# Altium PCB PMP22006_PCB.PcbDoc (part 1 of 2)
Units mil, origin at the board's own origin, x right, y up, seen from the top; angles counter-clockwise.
Board outline 2500 x 1522 mil, 4 copper layers (Top Layer, Signal Layer 1, Signal Layer 2, Bottom Layer), stack 186.034 mil thick; 52 components, 32 nets, 135 pads, 25 vias.
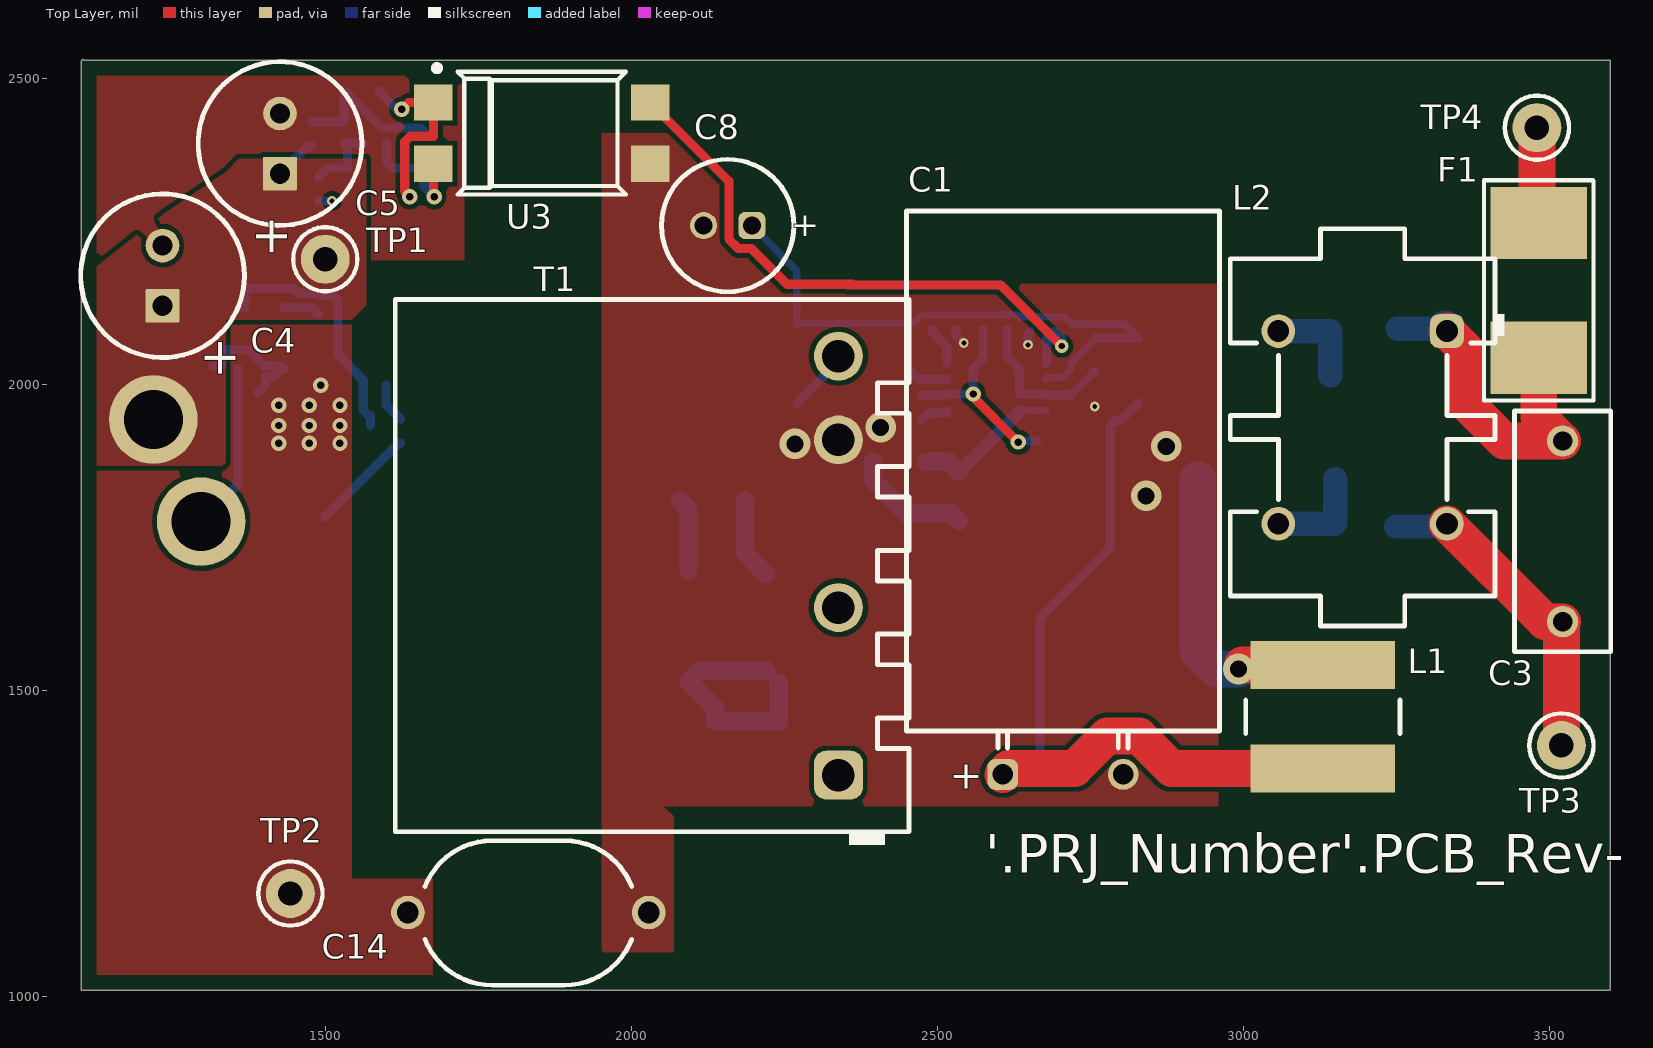
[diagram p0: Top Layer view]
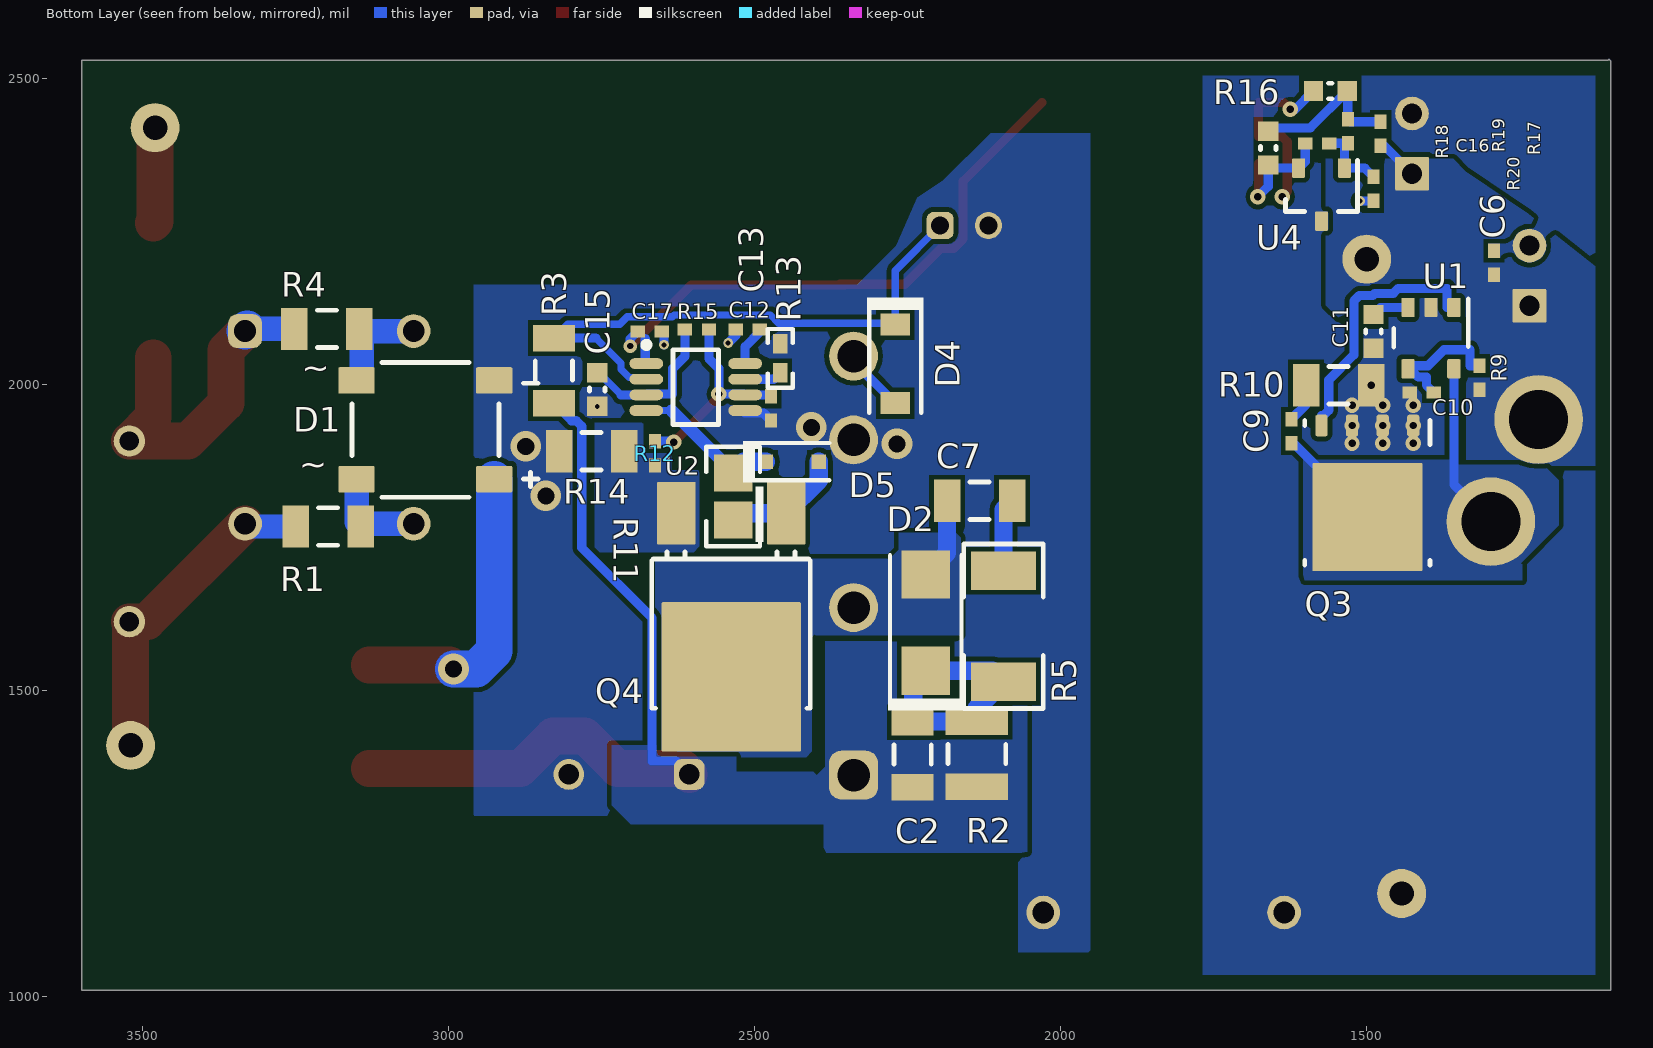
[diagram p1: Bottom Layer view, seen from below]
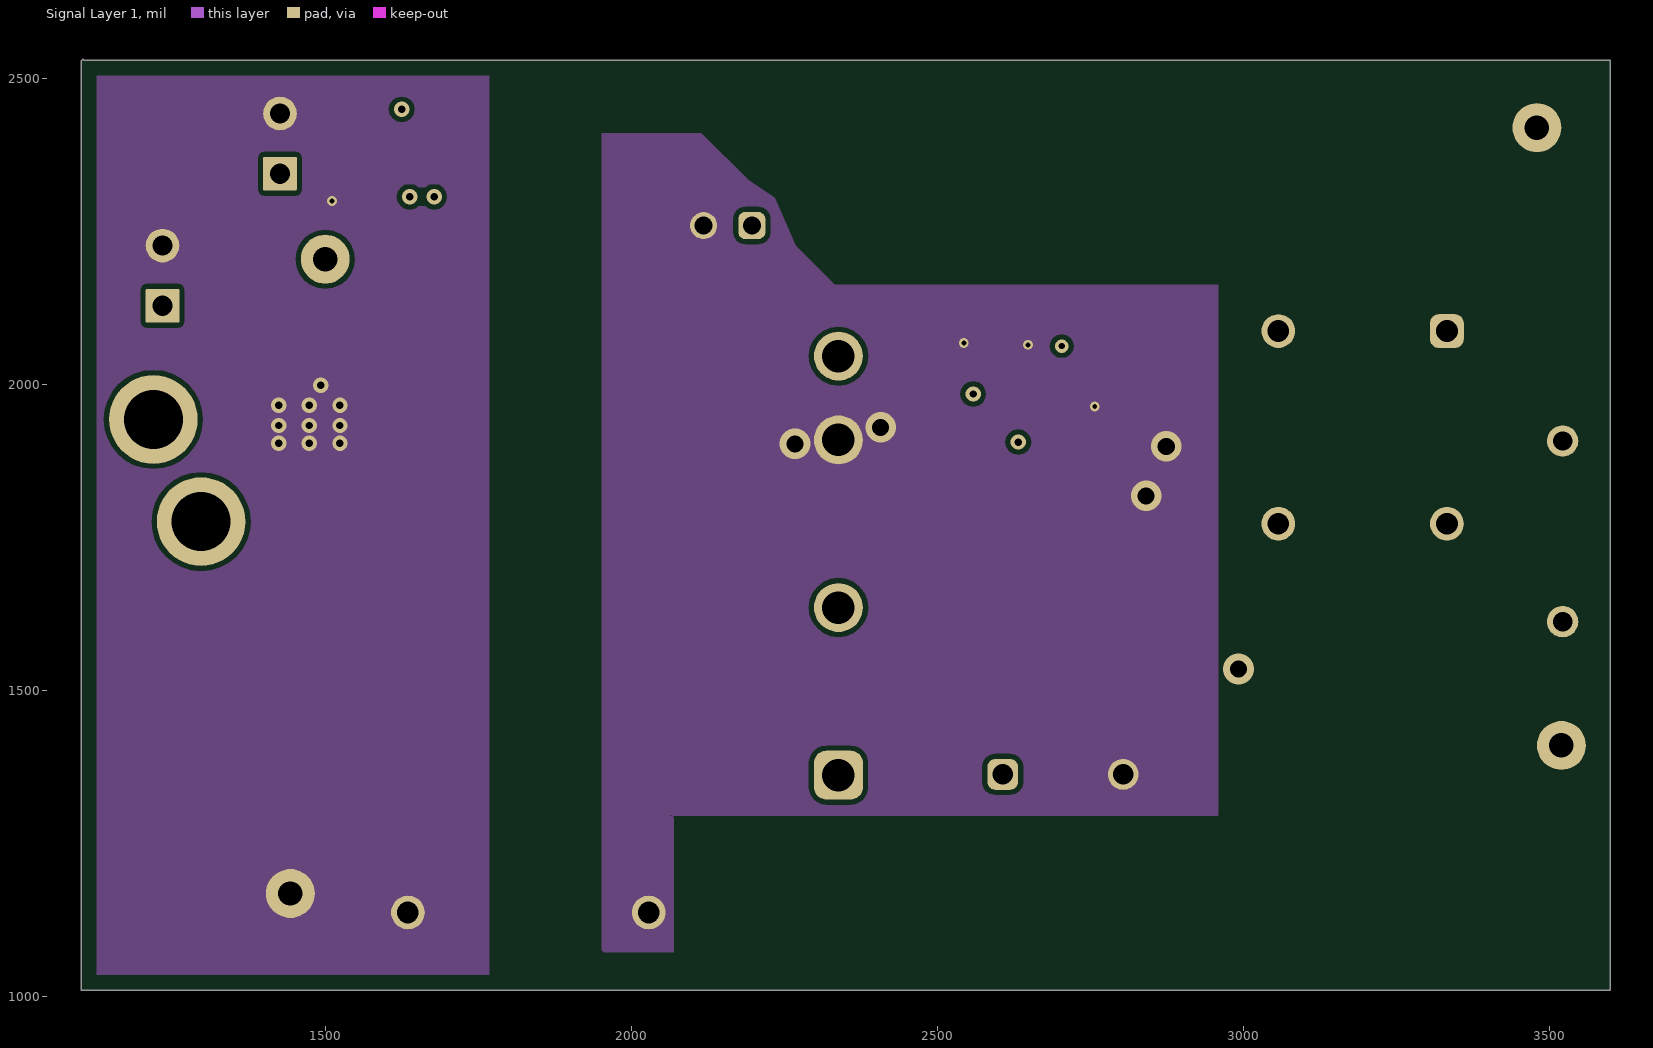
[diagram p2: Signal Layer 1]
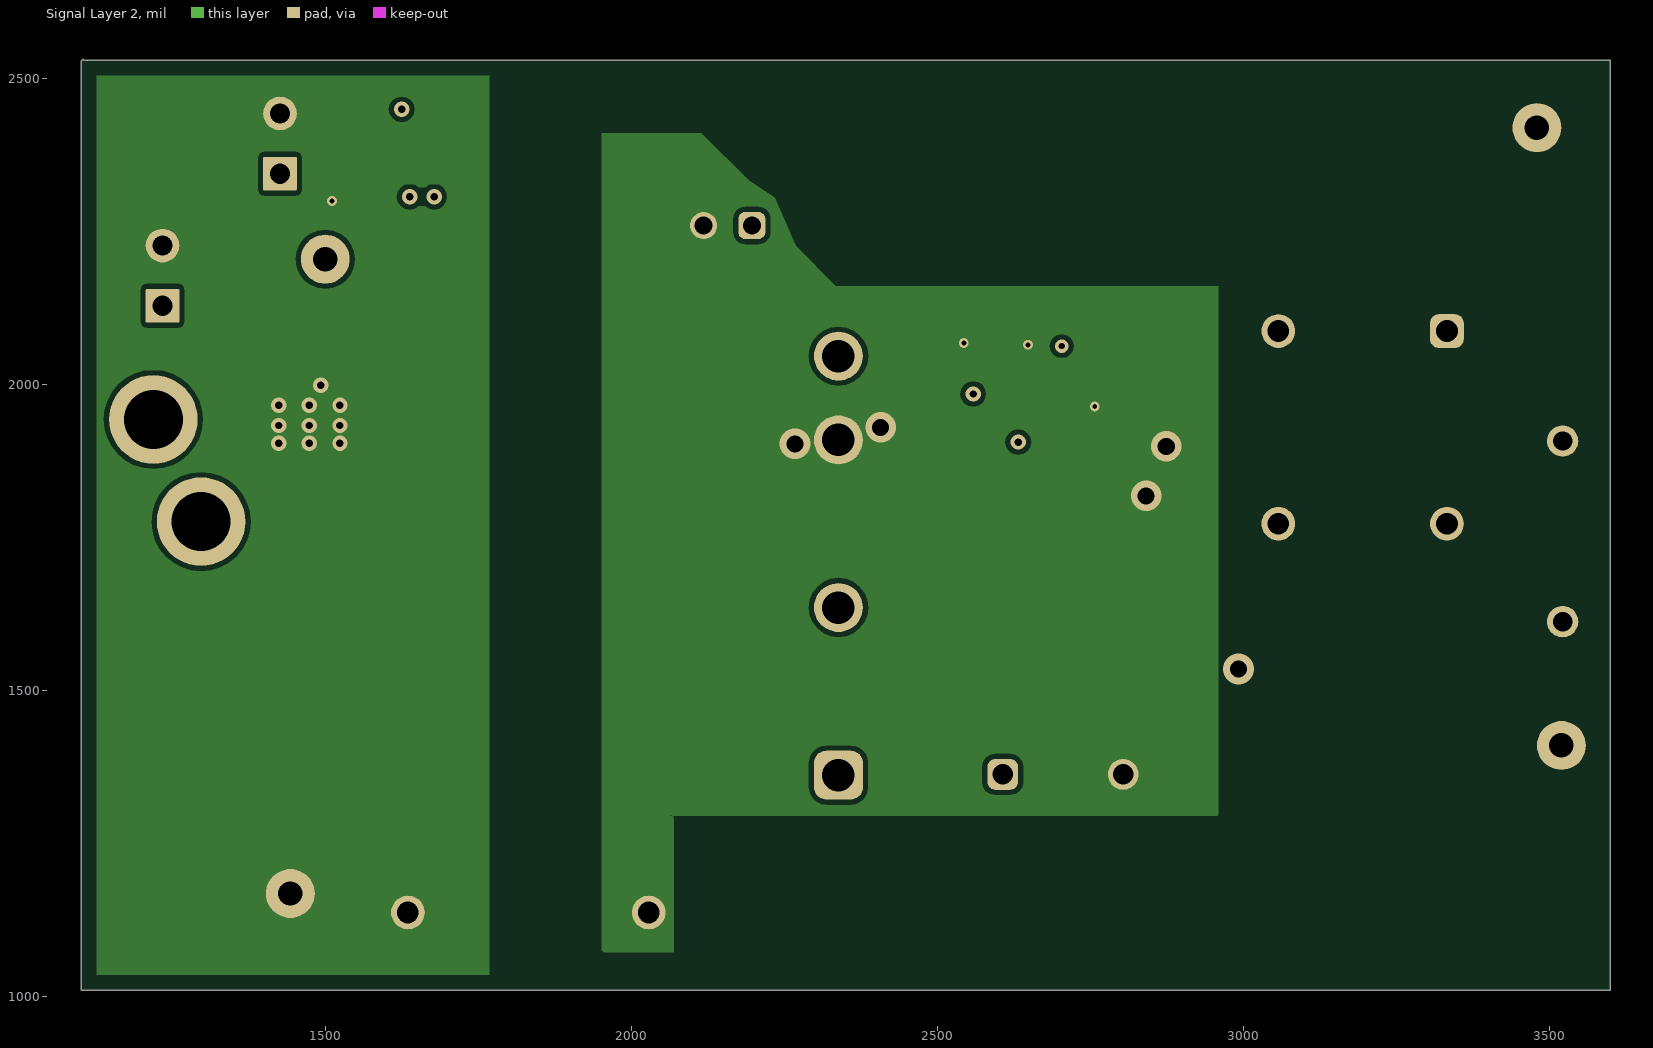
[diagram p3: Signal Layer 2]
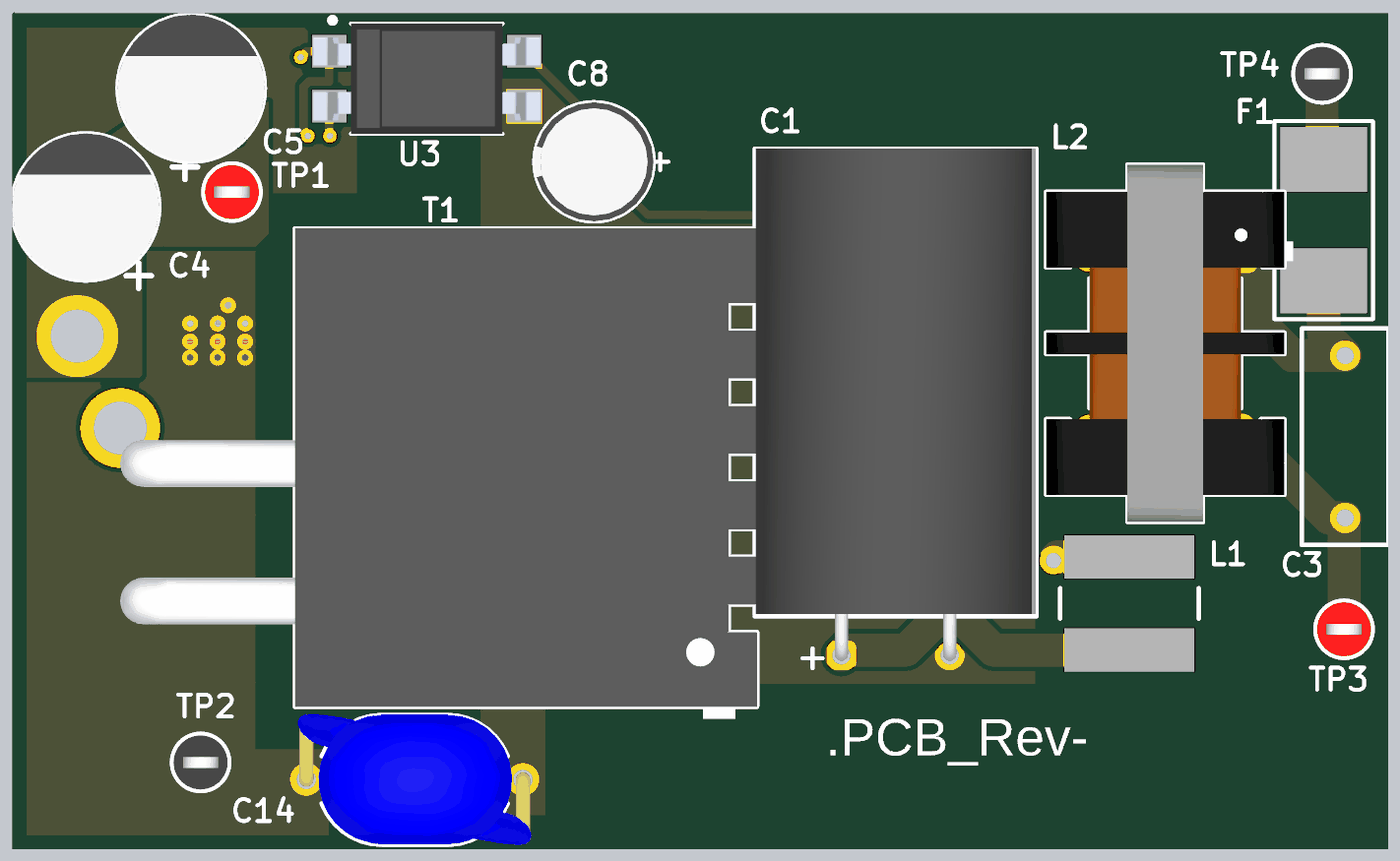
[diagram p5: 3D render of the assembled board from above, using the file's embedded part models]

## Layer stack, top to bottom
Top Solder: solder mask 0.4, Solder Resist, Dk 3.5
Top Layer: signal copper 2.8
Dielectric1: core 59.2, FR-4, Dk 4.8
Signal Layer 1: signal copper 1.417
Dielectric 2: core 59.2, FR-4, Dk 4.8
Signal Layer 2: signal copper 1.417
Dielectric 3: core 59.2, FR-4, Dk 4.8
Bottom Layer: signal copper 2.8
Bottom Solder: solder mask 0.4, Solder Resist, Dk 3.5

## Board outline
1100,1010 3600,1010 3600,2530 1105,2530 1103,2532 1100,2529

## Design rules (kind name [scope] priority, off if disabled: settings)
AcuteAngle [All] p1 off: minimum=4.50000000000000E+0001 checktracksonly=FALSE
AssemblyTestPointUsage [All] p1: valid=2
BoardOutlineClearance BoardOutlineClearance_MountingHoles [OnCopper and InComponentClass('Mounting Holes')] p1: gap=25 ignorepadtopadclearanceinfootprint=FALSE
BoardOutlineClearance BoardOutlineClearance_Poly [OnCopper and InPoly] p2: gap=25 ignorepadtopadclearanceinfootprint=FALSE
BoardOutlineClearance [OnCopper and Not InComponentClass('Logo') and not InComponentClass('FiducialMark') and not InRegion(1000,500,4000,800)] p3: gap=25 ignorepadtopadclearanceinfootprint=FALSE
Clearance Clearance_Keepouts [((IsTrack Or IsArc) And Not InPoly) And IsFree and IsKeepOut vs ((IsTrack Or IsArc) And Not InPoly) And IsFree and IsKeepOut] p1: gap=0 ignorepadtopadclearanceinfootprint=FALSE
Clearance Clearance_Poly [InPolygon] p2: gap=8 ignorepadtopadclearanceinfootprint=FALSE except(0: Arc-Hole Track-Hole SMDPad-Hole THPad-Hole Via-Hole Fill-Hole Poly-Hole Region-Hole Text-Hole)
Clearance [All] p3: gap=7.87 ignorepadtopadclearanceinfootprint=FALSE except(0: Arc-Hole Track-Hole SMDPad-Hole THPad-Hole Via-Hole Fill-Hole Poly-Hole Region-Hole Text-Hole)
ComponentClearance ComponentClearance_MountingHoles_FiducialMarks [InComponentClass('Mounting Holes') vs InComponentClass('FiducialMark')] p1: gap=50 collisioncheckmode=3 verticalgap=10 showdistances=FALSE
ComponentClearance ComponentClearance_Shunt [InComponentClass('Header') vs InComponentClass('Shunt')] p2: gap=0 collisioncheckmode=3 verticalgap=0 showdistances=FALSE
ComponentClearance ComponentClearance_Logo [InComponentClass('Logo')] p3: gap=50 collisioncheckmode=3 verticalgap=10 showdistances=FALSE
ComponentClearance ComponentClearance_ScrewToNut [(HasFootprint('NY PMS 440 0025 PH')) vs (HasFootprint('Keystone_1902C'))] p4: gap=5 collisioncheckmode=3 verticalgap=10 showdistances=FALSE
ComponentClearance ComponentClearance_MountingHoles [InComponentClass('Mounting Holes')] p5: gap=250 collisioncheckmode=3 verticalgap=100000 showdistances=FALSE
ComponentClearance ComponentClearance_SmallPassives [HasFootprint('0201*') or HasFootprint('0402*') or HasFootprint('0508') or HasFootprint('0603*') or HasFootprint('0612') or HasFootprint('0805*') or HasFootprint('0815*') or HasFootprint('0830*') or HasFootprint('1206*') or HasFootprint('1210*') or HasFootprint('1808*') or HasFootprint('1812*') or HasFootprint('1825*') or HasFootprint('2010*') or HasFootprint('2220*') or HasFootprint('2225*') or HasFootprint('2512*') or HasFootprint('2728*') or HasFootprint('3518*') vs HasFootprint('0201*') or HasFootprint('0402*') or HasFootprint('0508') or HasFootprint('0603*') or HasFootprint('0612') or HasFootprint('0805*') or HasFootprint('0815*') or HasFootprint('0830*') or HasFootprint('1206*') or HasFootprint('1210*') or HasFootprint('1808*') or HasFootprint('1812*') or HasFootprint('1825*') or HasFootprint('2010*') or HasFootprint('2220*') or HasFootprint('2225*') or HasFootprint('2512*') or HasFootprint('2728*') or HasFootprint('3518*')] p6: gap=14.96 collisioncheckmode=3 verticalgap=10 showdistances=FALSE
ComponentClearance ComponentClearance_THtoSMT [IsThruComponent vs IsSMTComponent] p7: gap=15 collisioncheckmode=3 verticalgap=30 showdistances=FALSE
ComponentClearance ComponentClearance_THtoTH [IsThruComponent vs IsThruComponent] p8: gap=10 collisioncheckmode=3 verticalgap=30 showdistances=FALSE
ComponentClearance [All] p9: gap=15 collisioncheckmode=3 verticalgap=10 showdistances=FALSE
DiffPairsRouting [All] p1: maxlimit=100 minlimit=10 mostfreqgap=10 toplayer_minwidth=15 toplayer_maxwidth=15 toplayer_prefwidth=15 midlayer1_minwidth=15 midlayer1_maxwidth=15 midlayer1_prefwidth=15 midlayer2_minwidth=15 midlayer2_maxwidth=15 midlayer2_prefwidth=15 bottomlayer_minwidth=15 bottomlayer_maxwidth=15 bottomlayer_prefwidth=15 maxuncoupledlength=1000
FabricationTestPointUsage TestPointUsage [All] p1: valid=2 allowmultiple=FALSE
FabricationTestpoint Testpoint [All] p1: side=3 testpointundercomponent=TRUE minsize=40 maxsize=100 preferedsize=60 minholesize=0 maxholesize=40 preferedholesize=32 testpointgrid=1 allowsidetop=TRUE allowsidebottom=TRUE usegrid=TRUE gridtolerance=0.01
FanoutControl Fanout_LCC [IsLCC] p1: bgadir=Out bgaviamode=Centered fanoutstyle=Auto fanoutdirection=Alternating viagrid=1 // Fanout_LCC (Default Rule)
FanoutControl Fanout_BGA [IsBGA] p2: bgadir=Out bgaviamode=Centered fanoutstyle=Auto fanoutdirection=Alternating viagrid=1 // Fanout_BGA (Default Rule)
FanoutControl Fanout_Default [All] p4: bgadir=Out bgaviamode=Centered fanoutstyle=Auto fanoutdirection=Alternating viagrid=1 // Fanout_Default (Default Rule)
FanoutControl Fanout_Small [(CompPinCount < 5)] p5: bgadir=Out bgaviamode=Centered fanoutstyle=Auto fanoutdirection=OutThenIn viagrid=1 // Fanout_Small (Default Rule)
HoleSize [All] p1: absolutevalues=TRUE maxlimit=251 minlimit=7.87 maxpercent=80.000 minpercent=20.000
MinimumAnnularRing MinimumAnnularRing_ThermalPadVias [IsVia and InAnyComponent] p1: minimumring=5.91
MinimumAnnularRing [All] p2: minimumring=7
MinimumSolderMaskSliver MinimumSolderMaskSliver_Logo [InComponentClass('Logo') vs InComponentClass('Logo')] p1 off: minsoldermaskwidth=0.7
MinimumSolderMaskSliver [All] p2 off: minsoldermaskwidth=3.94
PlaneConnect [All] p1: planeconnectstyle=Direct reliefexpansion=10 reliefentries=4 reliefconductorwidth=10 reliefairgap=10
PolygonConnect [All] p1: connectstyle=Direct reliefconductorwidth=10 reliefentries=4 polygonreliefangle="90 Angle" airgapwidth=10
RoutingVias ThermalPadVias [IsVia and InAnyComponent] p1: holewidth=7.87 width=19.68 viastyle="Through Hole" minholewidth=7.87 minwidth=19.68 maxholewidth=12.99 maxwidth=23.62
RoutingVias [All] p2: holewidth=16 width=34 viastyle="Through Hole" minholewidth=7.87 minwidth=26 maxholewidth=40 maxwidth=65
SilkToBoardRegionClearance [Not ((IsComment or IsDesignator) And (Hide <> 'False')) and not InRegion(1000,500,4000,800)] p1:
SilkToSilkClearance SilkToSilkClearance_Pb-FreeLogo [(HasFootprint('Pb-Free_Overlay_Medium') OR HasFootprint('Pb-Free_Overlay_Small')) vs (HasFootprint('Pb-Free_Overlay_Medium') OR HasFootprint('Pb-Free_Overlay_Small'))] p1: silktosilkclearance=0
SilkToSilkClearance [All] p2: silktosilkclearance=4
SilkToSolderMaskClearance SilkToComponentPadClearance [IsPad and InAnycomponent] p1: minsilkscreentomaskgap=0.5 clearancetoexposedcopper=TRUE
SilkToSolderMaskClearance "Silk to Solder Mask Opening" [All] p2: minsilkscreentomaskgap=0.5 clearancetoexposedcopper=FALSE
SolderMaskExpansion [All] p1: expansion=1.97
Width [All] p1: maxlimit=100 minlimit=6 preferedwidth=10 checkconnectedcopper=TRUE
15 further rules are at their usual default settings.

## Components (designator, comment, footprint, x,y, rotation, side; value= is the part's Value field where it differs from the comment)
C1 "UCS2D470MHD" Nichicon_1250x2000_HorizontalUP 2705,1717 r0 top value=47uF
C2 "GRM31A7U2J102JW31D" 1206L 2241.57,1395 r90 bottom value=1000pF
C3 "B32520C3104K289" B32520_1000x400x850 3522,1760 r90 top value=0.1uF
C4 "RS80J331MDNASQJT" S8_630x800 1233,2178 r90 top value=330uF
C5 "RS80J331MDNASQJT" S8_630x800 1425,2394 r90 top value=330uF
C6 "C1608X6S1A106M080AC" 0402L 1291,2199 r90 bottom value=10uF
C7 "VJ1206A100JXGAT5Z" 1206L 2132,1810 r0 bottom value=10pF
C8 "35YXH33MEFC5X11" Rubycon_500x1100 2157,2260 r180 top value=33uF
C9 "GRM1555C1H102JA01D" 0402L 1622,1924 r90 bottom value=1000pF
C10 "GRM155R60J105KE19D" 0402L 1409,1987 r0 bottom value=1uF
C11 "GRM188R61C225KAAD" 0603L 1488,2087 r270 bottom value=2.2uF
C12 "GRM155R71E473KA88D" 0402L 2511,2090 r180 bottom value=0.047uF
C13 "GRM1555C1H101JA01D" 0402L 2473,1961 r90 bottom value=100pF
C14 "CD45-E2GA222M-NKA" CD45_900x600x1300 1831,1137 r0 top value=2200pF
C15 "GRM188R61E105KA12D" 0603L 2757,1992 r270 bottom value=1uF
C16 "GRM155R71E473KA88D" 0402L 1580,2394.47 r180 bottom value=0.047uF
C17 "GRM1555C1H101JA01D" 0402L 2671,2087 r0 bottom value=100pF
D1 "CD-MBL206SL" CD-MBL2xxS 3038,1926 r0 bottom value=600V
D2 "ES1JTR" SMA 2220,1611 r90 bottom value=600V
D4 "BAV21W-7-F" SOD-123 2270,2034 r270 bottom value=200V
D5 "MMDL914-TP" SOD-323 2438,1874 r180 bottom value=100V
F1 "SSQ 2 /5K" 6125FA 3483,2154 r90 top
L1 "SRN6045-101M" SRN6045 3130,1457 r270 top value=100uH
L2 "UU9LFNP-B102" Sumida_UU9LF 3195,1930 r270 top value=1mH
Q3 "CSD18503Q5A" DQJ0008A 1498,1823 r270 bottom value=40V
Q4 "IPD65R650CEAUMA1" DPAK 2538,1656 r270 bottom value=650V
R1 "CRCW12060000Z0EA" 1206L 3197,1768 r180 bottom value=0
R2 "ERJ-14NF2003U" 1210L 2136.57,1396 r270 bottom value=200k
R3 "CRCW1206499KFKEA" 1206L 2828,2023 r270 bottom value=499k
R4 "CRCW12060000Z0EA" 1206L 3199,2091 r180 bottom value=0
R5 "CRCW2010261RFKEF" 2010 2093,1605 r270 bottom value=261
R9 "CRCW04020000Z0ED" 0402L 1315,2011 r90 bottom value=0
R10 "CRCW12064R70JNEA" 1206L 1545,1999 r180 bottom value=4.7
R11 "CRCW0402100RFKED" 0805M 2535,1817 r90 bottom value=100
R12 "CRCW0402100RFKED" 0402L 2662.32,1888 r90 bottom value=100
R13 "CRCW040251K1FKED" 0402 2458,2043 r270 bottom value=51.1k
R14 "CSR1206FKR250" 1206L 2766.32,1891 r0 bottom value=0.25
R15 "CRCW04021M00JNED" 0402L 2594,2090 r0 bottom value=1.0Meg
R16 "CRCW04021K20JNED" 0603L 1558.63,2480 r180 bottom value=1.2k
R17 "CRCW04020000Z0ED" 0402L 1476.36,2410 r270 bottom value=0
R18 "CRCW06031K00FKEA" 0603L 1660,2386.59 r270 bottom value=1.00k
R19 "CRCW040221K5FKED" 0402L 1530,2414.15 r90 bottom value=21.5k
R20 "CRCW04027K15FKED" 0402L 1488,2320 r90 bottom value=7.15k
T1 "RLTI-1250" Renco_RLTI-1250 1838,1704 r180 top value=400uH
TP1 "5000" Keystone5000 1499,2205 r90 top
TP2 "5001" Keystone5001 1442,1168 r90 top
TP3 "5000" Keystone5000 3520,1410 r90 top
TP4 "5001" Keystone5001 3480,2420 r90 top
U1 "UCC24612-1DBVT" DBV0005A_L 1394,2076 r270 bottom
U2 "LM5021MMX-1" MUA08A_L 2596,1996 r180 bottom
U3 "LTV-817A" DIP254P762X350-4 1853,2411 r0 top
U4 "TLV431ACDBZR" DBZ0003A_L 1573,2310.56 r270 bottom

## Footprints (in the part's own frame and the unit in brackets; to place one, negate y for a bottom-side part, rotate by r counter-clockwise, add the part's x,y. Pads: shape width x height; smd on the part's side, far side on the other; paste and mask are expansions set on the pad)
0402 [mm] "0402 from SM-752 data"
  rect 0.8x0.6 smd: 1(-0.6,0) 2(0.6,0)
  silkscreen extent -1.22,-0.52 1.22,0.52, body extent -0.55,-0.3 0.55,0.3, height 0.6
0402L [mm] "0402 from SM-752 data"
  rect 0.6x0.5 smd: 1(-0.5,0) 2(0.5,0)
  body extent -0.55,-0.3 0.55,0.3, height 0.6
0603L [mm] "0603 from SM-752 data"
  rect 0.8x0.85 smd: 1(-0.7,0) 2(0.7,0)
  silkscreen extent -0.07,-0.33 0.07,0.33, body extent -0.87,-0.47 0.87,0.47, height 1
0805M [mm] "0805 from SM-752 data"
  rect 1.55x1.6 smd: 1(-0.975,0) 2(0.975,0)
  silkscreen extent -2.07,-1.12 2.07,1.12, body extent -1.1,-0.72 1.1,0.72, height 1.45
1206L [mm] "1206 from SM-752 data"
  rect 1.1x1.75 smd: 1(-1.35,0) 2(1.35,0)
  silkscreen extent -0.4,-0.77 0.4,0.77, body extent -1.7,-0.9 1.7,0.9, height 1.35
1210L [mm] "1210 from SM-752 data"
  rect 1.1x2.6 smd: 1(-1.35,0) 2(1.35,0)
  silkscreen extent -0.4,-1.2 0.4,1.2, body extent -1.7,-1.35 1.7,1.35, height 1.35
2010 [mm] "Chip Capacitor, Body 5.08x2.54mm, IPC Medium Density"
  rect 1.6x2.7 smd: 1(-2.3,0) 2(2.3,0)
  silkscreen extent -3.42,-1.65 3.42,1.65, body extent -2.73,-1.45 2.73,1.45, height 1.66
6125FA [mm] "Cooper Bussman 6125FA Brick Fuses, recommended land pattern OC-2531 Rev. I 3/07"
  rect 3x4 smd: 1(-2.8,0) 2(2.8,0)
  silkscreen extent -4.57,-2.27 4.57,2.27, body extent -3.17,-1.42 3.17,1.41, height 2.84
B32520_1000x400x850 [mm] "TH, 2-Leads, Body 10x4mm, Lead Spacing 5mm"
  round 1.3 hole 0.8: 1(-3.75,0) 2(3.75,0)
  silkscreen extent -5,-2 5,2, body extent -5,-2 5,2, height 8.5
CD45_900x600x1300 [mm] "TH, 2-Leads, Dia 9mm, Pin Spacing 10 mm"
  round 1.4 hole 0.9: 1(-5,0) 2(5,0)
  silkscreen extent -4.29,-3.02 4.3,2.98, body extent -5.39,-3.01 5.39,3.01, height 13
CD-MBL2xxS [mm] "SMD, 4-Leads, Body 5.72x4.1mm"
  rrect9% 1.5x1.1 smd: 1(-2.86,2.05) 2(2.86,2.05) 3(2.86,-2.05) 4(-2.86,-2.05)
  silkscreen extent -4.67,-2.8 3.05,2.8, body extent -2.9,-2.65 2.9,2.65, height 1.02
DBV0005A_L [mm] "SOT23, 5-Leads, Body 2.9x1.6mm, Pitch 0.95mm, Lead Span 2.8mm, IPC High Density"
  rrect18% 0.8x0.55 smd: 1(-1.275,0.95) 2(-1.275,0) 3(-1.275,-0.95) 4(1.275,-0.95) 5(1.275,0.95)
  silkscreen extent -1.63,-1.55 0.38,1.55, body extent -1.42,-1.46 1.42,1.46, height 1.09
DBZ0003A_L [mm] "SOT23, 3-Leads, Body 2.9x1.3mm, Pitch 0.95mm, Lead Span 2.4mm, IPC High Density"
  rrect18% 0.8x0.55 smd: 1(-1.1,0.95) 2(-1.1,-0.95) 3(1.1,0)
  silkscreen extent -1.43,-1.5 0.7,1.5, body extent -1.26,-1.46 1.26,1.46, height 0.98
DIP254P762X350-4 [mm] "LITE-ON"
  rect 1.6x1.5 smd: 1(-4.5,1.27) 2(-4.5,-1.27) 3(4.5,-1.27) 4(4.5,1.27)
  silkscreen extent -4.47,-2.55 3.5,2.82, body extent -5.23,-2.55 5.23,2.55, height 4.62
DPAK [mm] "D-PAK, 3-Pads, Body 6.22x6.73mm (max), TO-252AA using nominal STEP model"
  rrect6% 2.6x1.6 smd: 1(-3.4,2.28) 3(-3.4,-2.28)
  rrect2% 6.2x5.8 smd paste-2.9: 4(3.4,0)
  silkscreen extent -4.5,-3.3 4.7,3.28, body extent -3.86,-3.29 5.84,3.29, height 2.48
DQJ0008A [mm] "SMD, 8-Leads, Body 5.75x4.9mm"
  rrect39% 0.91x0.51 smd paste-0.05 mask-0.05: 1(-2.795,1.905) 2(-2.795,0.635) 3(-2.795,-0.635) 4(-2.795,-1.905) 5(2.795,-1.905) 6(2.795,-0.635) 7(2.795,0.635) 8(2.795,1.905)
  rrect8% 1.58x1.25 on Bottom Paste: 9(-0.38,-1.45) 9(-0.38,0) 9(-0.38,1.45) 9(1.4,-1.45) 9(1.4,0) 9(1.4,1.45)
  rrect3% 3.48x4.47 on Bottom Solder: 9(0.55,0)
  rrect2% 4.49x4.57 smd paste-2.5 mask-2.5: 9(1.005,0)
  silkscreen extent -3,-2.6 3,2.6, body extent -3.13,-2.45 3.13,2.45, height 1.15
Keystone5000 [mil] "For Keystone 500x miniature loop terminals"
  round 80 hole 40: 1(0,0)
  silkscreen extent -52,-52 52,52, body extent -49,-49 49,49, height 182
Keystone5001 [mil] "For Keystone 500x miniature loop terminals"
  round 80 hole 40: 1(0,0)
  silkscreen extent -52,-52 52,52, body extent -49,-49 49,49, height 182
MUA08A_L [mm] "TSOP, 8-Leads, Body 3x3mm, Pitch 0.65mm, IPC High Density"
  oval 1.4x0.45 smd: 1(-2.05,0.975) 2(-2.05,0.325) 3(-2.05,-0.325) 4(-2.05,-0.975) 5(2.05,-0.975) 6(2.05,-0.325) 7(2.05,0.325) 8(2.05,0.975)
  silkscreen extent -2.17,-1.55 0.95,1.87, body extent -1.6,-1.6 1.6,1.6, height 1.09
Nichicon_1250x2000_HorizontalUP [mm] "TH, 2-Leads, Dia 12.5mm, Lead Spacing 5mm"
  rrect50% 1.275x1.275 hole 0.85: 1(-2.5,-9)
  round 1.275 hole 0.85: 2(2.5,-9)
  silkscreen extent -6.5,-7.9 6.5,14.4, body extent -6.5,-9.25 6.5,14.4, height 13.02
Renco_RLTI-1250 [mm] "TH, 8-Leads, Body 870x840mil"
  rrect50% 2.03x2.03 hole 1.35: 1(-12.7,8.699)
  round 2.03 hole 1.35: 3(-12.7,1.74) 5(-12.7,-5.22) 6(-12.7,-8.7)
  round 3.68 hole 2.45: A(15.748,-6.071) B(13.767,-1.829)
  silkscreen extent -15.63,-11.05 5.7,11.6, body extent -15.63,-11.05 13.77,11.05, height 13.72
Rubycon_500x1100 [mm] "TH, 2-Leads, Dia 5mm,  Lead Spacing 2mm"
  rrect50% 1.125x1.125 hole 0.75: 1(-1,0)
  round 1.125 hole 0.75: 2(1,0)
  silkscreen extent -2.75,-2.75 2.75,2.75, body extent -2.73,-2.75 2.75,2.75, height 12.51
S8_630x800 [mm] "NICHICON"
  rrect7% 1.4x1.4 hole 0.838: 1(-1.25,0)
  round 1.4 hole 0.838: 2(1.25,0)
  silkscreen extent -3.4,-3.4 3.4,3.4, body extent -3.4,-3.39 3.4,3.39, height 9.01
SMA [mm] "Molded Diode, 2-Leads, Body 4.3x2.6mm, IPC Medium Density, based on OnSemi component dimensions and land pattern"
  rect 2x2 smd: 1(-2,0) 2(2,0)
  silkscreen extent -3.66,-1.57 2.79,1.57, body extent -2.6,-1.3 2.6,1.3, height 2.42
SOD-123 [mm] "On Semi recommended land pattern"
  rect 0.915x1.22 smd: 1(-1.637,0) 2(1.637,0)
  silkscreen extent -2.74,-1.17 2.03,1.17, body extent -1.93,-0.9 1.93,0.9, height 1.35
SOD-323 [mm] "NXP recommended land pattern"
  rect 0.6x0.6 smd paste-0.05: 1(-1.1,0) 2(1.1,0)
  silkscreen extent -2.06,-0.86 1.53,0.86, body extent -1.3,-0.67 1.3,0.68, height 1.1
SRN6045 [mm] "SMD, 2-Leads, Body 6x6mm"
  rect 2x6 smd: 1(-2.15,0) 2(2.15,0)
  silkscreen extent -0.7,-3.2 0.7,3.2, body extent -3.2,-3.2 3.2,3.2, height 4.5
Sumida_UU9LF [mm] "TH, 4-Leads, Body 11x16.5mm"
  rrect50% 1.4x1.4 hole 0.9: 1(-4,3.5)
  round 1.4 hole 0.9: 2(-4,-3.5) 3(4,-3.5) 4(4,3.5)
  silkscreen extent -8.25,-5.5 8.25,5.9, body extent -8.25,-5.5 8.25,5.5, height 16.51

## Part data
C1: library part CMP-0076769-1, "CAP, AL, 47 µF, 200 V, +/- 20%, TH", Cap_Case=12.5x20mm, Manufacturer=Nichicon, Supplier Part Number 1=UCS2D470MHD-ND, Tolerance_%=20%, Value2=200V, ValueDisplayed=47µF
C2: "CAP, CERM, 1000 pF, 630 V,+/- 5%, U2J, 1206", Cap_Case=1206, Manufacturer=MuRata, Supplier Part Number 1=490-4296-1-ND, TempCo=U2J, Tolerance_%=5, Value2=630V, ValueDisplayed=1000pF
C3: "CAP, Film, 0.1 µF, 250 V, +/- 10%, TH", Cap_Case=10x4x8.5mm, Manufacturer=TDK, Supplier Part Number 1=495-2426-1-ND, Tolerance_%=10, Value1=Unknown, Value2=250V, ValueDisplayed=0.1µF
C4 C5: "CAP, Aluminum Polymer, 330 µF, 6.3 V,+/- 20%, 0.008 ohm, TH", Cap_Case=6.3X8mm, Manufacturer=Nichicon, Supplier Part Number 1=493-4039-1-ND, Tolerance_%=20, Value1="0.008 ohm", Value2=6.3V, ValueDisplayed=330µF
C6: "CAP, CERM, 10 µF, 10 V,+/- 10%, X6S, 0603", Cap_Case=0603, Manufacturer=TDK, Supplier Part Number 1=445-9019-1-ND, TempCo=X6S, Tolerance_%=10, Value1="0.004639 ohm", Value2=10V, ValueDisplayed=10µF
C7: "CAP, CERM, 10 pF, 1000 V,+/- 5%, C0G/NP0, 1206", Cap_Case=1206, Manufacturer=Vishay-Vitramon, Supplier Part Number 1=720-1010-1-ND, TempCo=C0G/NP0, Tolerance_%=5, Value2=1000V, ValueDisplayed=10pF
C8: "CAP, AL, 33 µF, 35 V, +/- 20%, TH", Cap_Case=5x11mm, Manufacturer=Rubycon, Supplier Part Number 1=35YXH33MEFC5X11-ND, Tolerance_%=20, Value1=Unknown, Value2=35V, ValueDisplayed=33µF
C9: "CAP, CERM, 1000 pF, 50 V,+/- 5%, C0G/NP0, 0402", Cap_Case=0402, Manufacturer=MuRata, Supplier Part Number 1=490-3244-1-ND, TempCo=C0G/NP0, Tolerance_%=5, Value2=50V, ValueDisplayed=1000pF
C10: "CAP, CERM, 1 µF, 6.3 V, +/- 10%, X5R, 0402", Cap_Case=0402, Manufacturer=MuRata, Supplier Part Number 1=490-1320-1-ND, TempCo=X5R, Tolerance_%=10, Value1=Unknown, Value2=6.3V, ValueDisplayed=1µF
C11: "CAP, CERM, 2.2 µF, 16 V,+/- 10%, X5R, 0603", Cap_Case=0603, Manufacturer=MuRata, TempCo=X5R, Tolerance_%=10, Value1=Unknown, Value2=16V, ValueDisplayed=2.2µF
C12 C16: "CAP, CERM, 0.047 µF, 25 V, +/- 10%, X7R, 0402", Cap_Case=0402, Manufacturer=MuRata, Supplier Part Number 1=490-3254-1-ND, TempCo=X7R, Tolerance_%=10, Value1=Unknown, Value2=25V, ValueDisplayed=0.047µF
C13 C17: "CAP, CERM, 100 pF, 50 V,+/- 5%, C0G/NP0, 0402", Cap_Case=0402, Manufacturer=MuRata, Supplier Part Number 1=81-GRM1555C1H101JA1D, TempCo=C0G/NP0, Tolerance_%=5, Value1=Unknown, Value2=50V, ValueDisplayed=100pF
C14: "CAP, CERM, 2200 pF,  V, +/- 20%, E, D9xT6mm", Cap_Case=9x6x13mm, Manufacturer=TDK, Supplier Part Number 1=445-174537-ND, TempCo=E, Tolerance_%=20, Value1=Unknown, Value2=V, ValueDisplayed=2200pF
C15: "CAP, CERM, 1 µF, 25 V, +/- 10%, X5R, 0603", Cap_Case=0603, Manufacturer=MuRata, Supplier Part Number 1=490-3897-1-ND, TempCo=X5R, Tolerance_%=10, Value1=Unknown, Value2=25V, ValueDisplayed=1µF
D1: "Diode, P-N-Bridge, 600 V, 2 A, 5.8x5.3mm", Manufacturer=Bourns, Supplier Part Number 1=CD-MBL206SLCT-ND, Value1=2A, Value2=0.96V
D2: "Diode, Superfast Rectifier, 600 V, 1 A, SMA", Manufacturer="SMC Diode Solutions", Supplier Part Number 1=1655-1425-1-ND, Value1=1A, Value2=1.7V
D4: "Diode, Switching, 200 V, 0.2 A, SOD-123", Manufacturer="Diodes Inc.", Supplier Part Number 1=BAV21W-FDICT-ND, Value1=0.2A, Value2=1.25V
D5: "Diode, Switching, 100 V, 0.2 A, SOD-323", Manufacturer="Micro Commercial Components", Supplier Part Number 1=MMDL914-TPMSCT-ND, Value1=0.2A, Value2=1V
F1: library part 6125FA2A, "Fuse, 2 A, 125VAC/VDC, SMD", Irating_A=2, Manufacturer="Bel Fuse Inc."
L1: library part SRN6045-680M, "FIXED IND 100UH 700MA 494 MOHM", Manufacturer=Bourns, Value1="0.351 ohm", Value2=0.9A, ValueDisplayed=100µH
L2: "Coupled inductor, 1 mH,  A, 0.35 ohm, TH", Manufacturer=Sumida, Supplier Part Number 1=308-1374-ND, ValueDisplayed=1mH
Q3: "MOSFET, N-CH, 40 V, 100 A, DQJ0008A (VSONP-8)", Alternate Manufacturer=None, Manufacturer="Texas Instruments", Supplier Part Number 1=296-30571-1-ND, Value1="0.0062 ohm", Value2="13 nC"
Q4: "MOSFET, N-CH, 650 V, 10.1 A, DPAK", Alternate Manufacturer=None, Manufacturer="Infineon Technologies", Supplier Part Number 1=IPD65R650CEAUMA1-ND, Value1="? ohm", Value2="23 nC"
R1 R4: "RES, 0, 5%, 0.25 W, 1206", Manufacturer=Vishay-Dale, Power_W=0.25, Supplier Part Number 1=541-0.0ECT-ND, TempCo="200 ppm/C", Tolerance_%=5, Value1=5%, Value2=0.25W, Value_Code=0000, ValueDisplayed=0
R2: "RES, 200 k, 1%, 0.5 W, 1210", Manufacturer=Panasonic, Power_W=0.5, Supplier Part Number 1=P200KAACT-ND, TempCo="100 ppm/C", Tolerance_%=1, Value1=1%, Value2=0.5W, Value_Code=200k
R3: "RES, 499 k, 1%, 0.25 W, 1206", Manufacturer=Vishay-Dale, Power_W=0.25, Supplier Part Number 1=541-499KFCT-ND, TempCo="100 ppm/C", Tolerance_%=1, Value1=1%, Value2=0.25W, Value_Code=499k
R5: library part CMP-0016331-2, "RES, 261, 1%, 0.75 W, AEC-Q200 Grade 0, 2010", Manufacturer=Vishay-Dale, Power_W=750mW, Supplier Part Number 1=541-261ACCT-ND, TempCo="100 ppm/C", Tolerance_%=1%, Value2=0.75W, Value_Code=261R, ValueDisplayed=261
R9 R17: "RES, 0, 5%, 0.063 W, 0402", Manufacturer=Vishay-Dale, Power_W=0.063, Supplier Part Number 1=541-0.0JCT-ND, TempCo="200 ppm/C", Tolerance_%=5, Value1=5%, Value2=0.063W, Value_Code=0000, ValueDisplayed=0
R10: "RES, 4.7, 5%, 0.25 W, 1206", Manufacturer=Vishay-Dale, Power_W=0.25, Supplier Part Number 1=541-4.7ECT-ND, TempCo="200 ppm/C", Tolerance_%=5, Value1=5%, Value2=0.25W, Value_Code=4R70, ValueDisplayed=4.7
R11 R12: "RES, 100, 1%, 0.063 W, 0402", Manufacturer=Vishay-Dale, Power_W=0.063, Supplier Part Number 1=541-100LCT-ND, TempCo="100 ppm/C", Tolerance_%=1, Value1=1%, Value2=0.063W, Value_Code=100R, ValueDisplayed=100
R13: "RES, 51.1 k, 1%, 0.063 W, 0402", Manufacturer=Vishay-Dale, Power_W=0.063, Supplier Part Number 1=541-51.1KLCT-ND, TempCo="100 ppm/C", Tolerance_%=1, Value1=1%, Value2=0.063W, Value_Code=51k1, ValueDisplayed=51.1k
R14: "RES, 0.25, 1%, 0.5 W, 1206", Manufacturer="Stackpole Electronics Inc", Power_W=0.5, Supplier Part Number 1=CSR1206FKR250CT-ND, TempCo="100 ppm/C", Tolerance_%=1, Value1=1%, Value2=0.5W, Value_Code=R250, ValueDisplayed=0.25
R15: "RES, 1.0 M, 5%, 0.063 W, 0402", Manufacturer=Vishay-Dale, Power_W=0.063, Supplier Part Number 1=541-1.0MJCT-ND, TempCo="200 ppm/C", Tolerance_%=5, Value1=5%, Value2=0.063W, Value_Code=1M00, ValueDisplayed=1.0M
R16: "RES, 1.2 k, 5%, 0.063 W, 0402", Manufacturer=Vishay-Dale, Power_W=0.063, Supplier Part Number 1=541-1.2KJCT-ND, TempCo="200 ppm/C", Tolerance_%=5, Value1=5%, Value2=0.063W, Value_Code=1k20, ValueDisplayed=1.2k
R18: "RES, 1.00 k, 1%, 0.1 W, 0603", Manufacturer=Vishay-Dale, Power_W=0.1, Supplier Part Number 1=541-1.00KHCT-ND, TempCo="100 ppm/C", Tolerance_%=1, Value1=1%, Value2=0.1W, Value_Code=1k00, ValueDisplayed=1.00k
R19: "RES, 21.5 k, 1%, 0.063 W, 0402", Manufacturer=Vishay-Dale, Power_W=0.063, Supplier Part Number 1=541-21.5KLCT-ND, TempCo="100 ppm/C", Tolerance_%=1, Value1=1%, Value2=0.063W, Value_Code=21k5, ValueDisplayed=21.5k
R20: "RES, 7.15 k, 1%, 0.063 W, 0402", Manufacturer=Vishay-Dale, Power_W=0.063, Supplier Part Number 1=541-7.15KLCT-ND, TempCo="100 ppm/C", Tolerance_%=1, Value1=1%, Value2=0.063W, Value_Code=7k15, ValueDisplayed=7.15k
T1: library part CMP-0076771-1, "Transformer, 400 uH, TH", Manufacturer="Renco Electronics", ValueDisplayed=400µH
TP1: "Test Point, Miniature, Red, TH", Color=Red, Manufacturer=Keystone, Supplier Part Number 1=36-5000-ND
TP2: "Test Point, Miniature, Black, TH", Color=Black, Manufacturer=Keystone, Supplier Part Number 1=36-5001-ND
TP3: library part CMP-0055137-1, "Test Point, Miniature, Red, TH", Color=Red, Manufacturer=Keystone, Supplier Part Number 1=36-5000-ND
TP4: library part CMP-0055138-1, "Test Point, Miniature, Black, TH", Color=Black, Manufacturer=Keystone, Supplier Part Number 1=36-5001-ND
U1: library part UCC24612-2DBVT, "UCC24612-1DBV, DBV0005A (SOT-23-5)", Alternate Manufacturer="Texas Instruments"
U2: "AC-DC Current Mode PWM Controller, 8-pin MSOP", Manufacturer="Texas Instruments", PackageTopMarking=ZXTT*21-1, PowerWise=N
U3: library part LTV-817S, "Optocoupler, 5 kV, 50-600% CTR, SMT", Manufacturer=Lite-On, Supplier Part Number 1=160-1367-5-ND, Voltage_Isolation_Vrms=5000V
U4: "Low Voltage Adjustable Precision Shunt Regulator, 39 ppm / degC, 15 mA, 0 to 70 degC, 3-pin SOT-23 (DBZ), Green (RoHS & no Sb/Br)", Alternate Manufacturer="Texas Instruments", Alternate PartNumber=Equivalent, Rating=Catalog, Supplier Part Number 1=296-18912-2-ND, Temp Coeff(Max)(ppm/ degree C)=129, Temp Coeff(Typ)(ppm/ degree C)=39

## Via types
v1: diameter 25, hole 12, Top Layer to Bottom Layer, 15 vias
v2: diameter 50, hole 28, Top Layer to Bottom Layer, 5 vias
v3: diameter 16, hole 8, Top Layer to Bottom Layer, 4 vias
v4: diameter 22, hole 10, Top Layer to Bottom Layer, 1 vias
